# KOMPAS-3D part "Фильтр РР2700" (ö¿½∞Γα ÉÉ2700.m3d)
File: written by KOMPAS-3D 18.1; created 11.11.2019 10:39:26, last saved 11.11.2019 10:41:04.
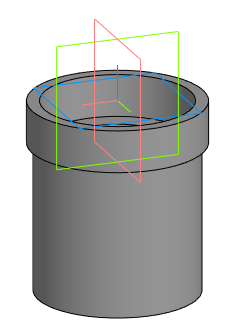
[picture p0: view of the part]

Document properties: Полное имя файла: D:\Magna\Магна Ins\Магна ins 10\М10-00.00.000\3Д\Фильтр РР2700.m3d

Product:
- Part/product: Фильтр РР2700
    Масса: 1.04743

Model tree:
1. Эскиз:2  (with: Элемент выдавливания:1, Элемент выдавливания:3)  (labels: Фильтр РР2700)
2. Элемент выдавливания:1
     Расстояние 1 = 17
3. Эскиз:4  (with: Элемент выдавливания:1)
4. Элемент выдавливания:2
     Расстояние 1 = 60

Referenced files in D:\Magna\Магна Ins\Магна ins 10\М10-00.00.000\3Д\: Труба 1165 для фильтра.a3d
